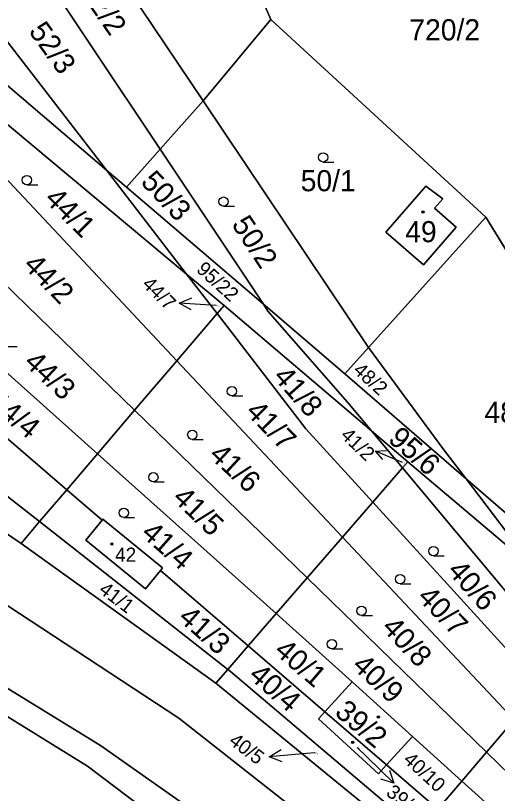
# Model space of a CAD drawing. Extents: x -598233 to -596890, y -1157848 to -1156431.
# Drawn here: x -597365.8 to -597327.1, y -1157018.9 to -1156956.3 of the extents above; entities that cross this region are included whole.
import ezdxf

# ---------------------------------------------------------------- set-up
doc = ezdxf.new("R2010")
doc.units = 0
for name, color, linetype in [('Level 1', 7, 'Continuous'), ('Level 4', 7, 'Continuous'), ('Level 5', 7, 'Continuous'), ('Level 57', 7, 'Continuous'), ('Level 60', 7, 'Continuous'), ('Vrstva 54', 7, 'Continuous'), ('Vrstva 60', 7, 'Continuous')]:
    doc.layers.add(name, color=color, linetype=linetype)

msp = doc.modelspace()

# ---------------------------------------------------------------- linework, layer by layer
at = {"layer": 'Level 1'}
for points in [[(-597345.28, -1156956.63), (-597347.92, -1156950.58), (-597357.71, -1156936.82)], [(-597350.74, -1156963.16), (-597361.74, -1156946.78), (-597363.49, -1156943.72)], [(-597354.19, -1156967.05), (-597365.22, -1156950.5), (-597366.91, -1156947.8)], [(-597316.36, -1157049.69), (-597321.33, -1157045.93), (-597360.03, -1157016.65), (-597390.17, -1156998.02), (-597420.96, -1156981.11), (-597456.97, -1156960.5), (-597484.08, -1156948.02)], [(-597315.54, -1157068.55), (-597316.36, -1157049.69), (-597316.57, -1157044.86), (-597315.03, -1157042.41), (-597313.54, -1157040.04), (-597313.01, -1157039.2), (-597311.84, -1157037.35), (-597310.56, -1157035.31), (-597309.44, -1157033.52), (-597308.22, -1157031.59), (-597306.57, -1157028.96), (-597305.61, -1157027.44), (-597304.81, -1157026.14), (-597303.64, -1157024.31), (-597310.64, -1157014.28), (-597312.61, -1157008.25), (-597315.16, -1156993.14), (-597321.82, -1156982.66), (-597324.52, -1156978.21), (-597328.01, -1156972.52), (-597345.28, -1156956.63), (-597347.92, -1156950.58)], [(-597370.84, -1156952.48), (-597371.09, -1156952.78), (-597370.52, -1156958.47), (-597358.5, -1156968.74)], [(-597370.84, -1156952.48), (-597369.28, -1156954.75), (-597358.5, -1156968.74)], [(-597345.28, -1156956.63), (-597350.74, -1156963.16)], [(-597345.28, -1156956.63), (-597328.01, -1156972.52)], [(-597350.74, -1156963.16), (-597354.19, -1156967.05)], [(-597350.74, -1156963.16), (-597337.44, -1156983)], [(-597352.06, -1156977.11), (-597367.63, -1156964.1)], [(-597369.51, -1156966.31), (-597352.84, -1156984.07)], [(-597354.19, -1156967.05), (-597356.9, -1156970.11)], [(-597354.19, -1156967.05), (-597345.89, -1156979.53)], [(-597358.5, -1156968.74), (-597356.9, -1156970.11)], [(-597358.5, -1156968.74), (-597352.06, -1156977.11)], [(-597356.9, -1156970.11), (-597345.89, -1156979.53)], [(-597332.82, -1156970.02), (-597331.47, -1156971.06), (-597332.13, -1156971.81), (-597330.39, -1156973.32), (-597333.02, -1156976.36), (-597336.04, -1156973.74), (-597332.82, -1156970.02)], [(-597373.63, -1156971.16), (-597356.24, -1156988.05)], [(-597419.12, -1156972.02), (-597386.6, -1156990.52), (-597352.68, -1157012.8), (-597315.03, -1157042.41)], [(-597337.44, -1156983), (-597328.01, -1156972.52)], [(-597312.61, -1157008.25), (-597315.16, -1156993.14), (-597321.82, -1156982.66), (-597324.52, -1156978.21), (-597328.01, -1156972.52)], [(-597349.05, -1156979.62), (-597352.06, -1156977.11)], [(-597352.06, -1156977.11), (-597349.61, -1156980.28)], [(-597422.56, -1156978.13), (-597419.84, -1156979.66), (-597389.18, -1156996.46), (-597358.98, -1157014.99), (-597316.57, -1157044.86)], [(-597380, -1156978.65), (-597361.68, -1156994.44)], [(-597349.05, -1156979.62), (-597349.61, -1156980.28)], [(-597349.05, -1156979.62), (-597337.2, -1156989.71)], [(-597345.89, -1156979.53), (-597339.35, -1156985.13)], [(-597345.89, -1156979.53), (-597345.53, -1156980.07), (-597339.13, -1156987.4), (-597337.2, -1156989.71)], [(-597349.61, -1156980.28), (-597352.84, -1156984.07)], [(-597349.61, -1156980.28), (-597342.48, -1156989.54), (-597337.1, -1156995.44)], [(-597382.92, -1156982.09), (-597363.87, -1156997)], [(-597369.98, -1156981.93), (-597359.22, -1156991.55)], [(-597339.35, -1156985.13), (-597337.44, -1156983)], [(-597329.6, -1156993.56), (-597331.38, -1156991.22), (-597337.44, -1156983)], [(-597352.84, -1156984.07), (-597356.24, -1156988.05)], [(-597352.84, -1156984.07), (-597339.53, -1156998.24)], [(-597385.43, -1156985.04), (-597365.36, -1156998.75)], [(-597339.35, -1156985.13), (-597329.6, -1156993.56)], [(-597356.24, -1156988.05), (-597359.22, -1156991.55)], [(-597356.24, -1156988.05), (-597342.37, -1157001.53)], [(-597337.2, -1156989.71), (-597334.28, -1156992.19)], [(-597334.71, -1156992.68), (-597337.2, -1156989.71)], [(-597359.22, -1156991.55), (-597361.68, -1156994.44)], [(-597359.22, -1156991.55), (-597344.87, -1157004.39)], [(-597334.28, -1156992.19), (-597334.71, -1156992.68)], [(-597324.09, -1157000.8), (-597334.28, -1156992.19)], [(-597334.71, -1156992.68), (-597337.1, -1156995.44)], [(-597334.71, -1156992.68), (-597321.73, -1157008.19)], [(-597329.6, -1156993.56), (-597312.61, -1157008.25)], [(-597329.6, -1156993.56), (-597324.09, -1157000.8)], [(-597361.68, -1156994.44), (-597363.87, -1156997)], [(-597361.68, -1156994.44), (-597358.85, -1156996.88)], [(-597337.1, -1156995.44), (-597339.53, -1156998.24)], [(-597337.1, -1156995.44), (-597323.54, -1157010.33)], [(-597363.87, -1156997), (-597365.36, -1156998.75)], [(-597363.87, -1156997), (-597348.75, -1157008.88)], [(-597358.85, -1156996.88), (-597360.17, -1156998.5), (-597355.37, -1157002.41), (-597354.16, -1157000.92)], [(-597354.16, -1157000.92), (-597353.99, -1157000.72), (-597358.79, -1156996.81), (-597358.85, -1156996.88)], [(-597339.53, -1156998.24), (-597342.37, -1157001.53)], [(-597339.53, -1156998.24), (-597325.74, -1157012.93)], [(-597365.36, -1156998.75), (-597349.72, -1157010)], [(-597354.16, -1157000.92), (-597347.11, -1157006.99)], [(-597342.37, -1157001.53), (-597344.87, -1157004.39)], [(-597342.37, -1157001.53), (-597327.96, -1157015.53)], [(-597344.87, -1157004.39), (-597347.11, -1157006.99)], [(-597344.87, -1157004.39), (-597338.74, -1157009.87)], [(-597347.11, -1157006.99), (-597348.75, -1157008.88)], [(-597347.11, -1157006.99), (-597340.95, -1157012.29)], [(-597348.75, -1157008.88), (-597349.72, -1157010)], [(-597348.75, -1157008.88), (-597348.54, -1157009.04), (-597333.37, -1157021.91)], [(-597338.74, -1157009.87), (-597340.95, -1157012.29)], [(-597333.91, -1157014.29), (-597338.74, -1157009.87)], [(-597349.72, -1157010), (-597334.09, -1157022.76)], [(-597340.95, -1157012.29), (-597341.47, -1157012.86), (-597336.64, -1157017.28), (-597335.99, -1157016.56)], [(-597340.95, -1157012.29), (-597335.99, -1157016.56)], [(-597325.74, -1157012.93), (-597327.96, -1157015.53)], [(-597335.99, -1157016.56), (-597333.91, -1157014.29)], [(-597333.91, -1157014.29), (-597329.94, -1157017.87)], [(-597327.96, -1157015.53), (-597329.94, -1157017.87)], [(-597327.96, -1157015.53), (-597310.75, -1157032.25)], [(-597335.99, -1157016.56), (-597331.86, -1157020.13)], [(-597329.94, -1157017.87), (-597331.86, -1157020.13)], [(-597329.94, -1157017.87), (-597318.23, -1157028.41)]]:
    msp.add_lwpolyline(points, dxfattribs=at)
at = {"layer": 'Level 5'}
for p, q in [((-597341.09, -1156968.09), (-597340.215, -1156968.09)), ((-597364.89, -1156969.92), (-597364.015, -1156969.92)), ((-597349.09, -1156971.65), (-597348.215, -1156971.65)), ((-597366.56, -1156982.93), (-597365.685, -1156982.93)), ((-597348.42, -1156986.89), (-597347.545, -1156986.89)), ((-597351.6, -1156990.39), (-597350.725, -1156990.39)), ((-597354.73, -1156993.81), (-597353.855, -1156993.81)), ((-597357.11, -1156996.67), (-597356.235, -1156996.67)), ((-597332.22, -1156999.75), (-597331.345, -1156999.75)), ((-597334.9, -1157002), (-597334.025, -1157002)), ((-597338, -1157004.55), (-597337.125, -1157004.55)), ((-597340.38, -1157007.23), (-597339.505, -1157007.23))]:
    msp.add_line(p, q, dxfattribs=at)
for centre, radius in [((-597341.09, -1156967.715), 0.375), ((-597364.89, -1156969.545), 0.375), ((-597349.09, -1156971.275), 0.375), ((-597333.05, -1156972.1), 0.09), ((-597333.05, -1156972.1), 0.0521), ((-597348.42, -1156986.515), 0.375), ((-597351.6, -1156990.015), 0.375), ((-597354.73, -1156993.435), 0.375), ((-597357.11, -1156996.295), 0.375), ((-597358.07, -1156998.8), 0.09), ((-597358.07, -1156998.8), 0.0521), ((-597332.22, -1156999.375), 0.375), ((-597334.9, -1157001.625), 0.375), ((-597338, -1157004.175), 0.375), ((-597340.38, -1157006.855), 0.375), ((-597336.64, -1157012.7), 0.09), ((-597336.64, -1157012.7), 0.0521), ((-597338.72, -1157014.75), 0.09), ((-597338.72, -1157014.75), 0.0521)]:
    msp.add_circle(centre, radius, dxfattribs=at)
at = {"layer": 'Level 57'}
for p, q in [((-597349.69, -1156979.62), (-597352.646, -1156979.432)), ((-597334.71, -1156992.24), (-597336.869, -1156991.349)), ((-597338.35, -1157015.16), (-597337.54, -1157015.948)), ((-597342.421, -1157015.655), (-597345.411, -1157015.902)), ((-597341.76, -1157015.6), (-597342.421, -1157015.655)), ((-597337.54, -1157015.948), (-597335.39, -1157018.04))]:
    msp.add_line(p, q, dxfattribs=at)
for points in [[(-597351.692, -1156979.987), (-597352.646, -1156979.432), (-597351.629, -1156979.002)], [(-597336.298, -1156992.006), (-597336.869, -1156991.349), (-597336.001, -1156991.286)], [(-597344.373, -1157016.318), (-597345.411, -1157015.902), (-597344.455, -1157015.321)], [(-597335.758, -1157016.984), (-597335.39, -1157018.04), (-597336.455, -1157017.701)]]:
    msp.add_lwpolyline(points, dxfattribs=at)
at = {"layer": 'Level 60'}
for points in [[(-597451.05, -1156953.86), (-597464.61, -1156946.36), (-597548.33, -1156902.86), (-597534.86, -1156896.71), (-597497.72, -1156917.84), (-597462.51, -1156937.89), (-597461.2, -1156938.63), (-597445.67, -1156947.81), (-597407.63, -1156970.82), (-597406.11, -1156971.52), (-597385.43, -1156985.04), (-597365.36, -1156998.75), (-597349.72, -1157010), (-597334.09, -1157022.76), (-597314.86, -1157038.93), (-597313.54, -1157040.04), (-597315.03, -1157042.41), (-597352.68, -1157012.8), (-597386.6, -1156990.52), (-597419.12, -1156972.02)], [(-597405.88, -1156927.58), (-597393.79, -1156938.04), (-597383.92, -1156946.41), (-597381.56, -1156948), (-597378.88, -1156947.67), (-597375.93, -1156946.59), (-597375.26, -1156946.02), (-597370.84, -1156952.48), (-597371.09, -1156952.78), (-597370.52, -1156958.47), (-597358.5, -1156968.74), (-597352.06, -1156977.11), (-597367.63, -1156964.1), (-597384.93, -1156949.57), (-597385.23, -1156949.57)], [(-597350.74, -1156963.16), (-597361.74, -1156946.78), (-597363.49, -1156943.72), (-597357.71, -1156936.82), (-597347.92, -1156950.58), (-597345.28, -1156956.63)], [(-597354.19, -1156967.05), (-597365.22, -1156950.5), (-597366.91, -1156947.8), (-597363.49, -1156943.72), (-597361.74, -1156946.78), (-597350.74, -1156963.16)], [(-597365.22, -1156950.5), (-597354.19, -1156967.05), (-597356.9, -1156970.11), (-597358.5, -1156968.74), (-597369.28, -1156954.75), (-597370.84, -1156952.48), (-597366.91, -1156947.8)], [(-597419.84, -1156979.66), (-597389.18, -1156996.46), (-597358.98, -1157014.99), (-597316.57, -1157044.86), (-597316.36, -1157049.69), (-597321.33, -1157045.93), (-597360.03, -1157016.65), (-597390.17, -1156998.02), (-597420.96, -1156981.11), (-597456.97, -1156960.5), (-597484.08, -1156948.02), (-597453.24, -1156960.9), (-597422.56, -1156978.13)], [(-597370.52, -1156958.47), (-597371.09, -1156952.78), (-597370.84, -1156952.48), (-597369.28, -1156954.75), (-597358.5, -1156968.74)], [(-597328.01, -1156972.52), (-597337.44, -1156983), (-597350.74, -1156963.16), (-597345.28, -1156956.63)], [(-597339.35, -1156985.13), (-597345.89, -1156979.53), (-597354.19, -1156967.05), (-597350.74, -1156963.16), (-597337.44, -1156983)], [(-597367.63, -1156964.1), (-597352.06, -1156977.11), (-597349.61, -1156980.28), (-597352.84, -1156984.07), (-597369.51, -1156966.31)], [(-597356.24, -1156988.05), (-597373.63, -1156971.16), (-597369.51, -1156966.31), (-597352.84, -1156984.07)], [(-597345.89, -1156979.53), (-597356.9, -1156970.11), (-597354.19, -1156967.05)], [(-597345.89, -1156979.53), (-597345.53, -1156980.07), (-597339.13, -1156987.4), (-597337.2, -1156989.71), (-597349.05, -1156979.62), (-597352.06, -1156977.11), (-597358.5, -1156968.74), (-597356.9, -1156970.11)], [(-597332.82, -1156970.02), (-597331.47, -1156971.06), (-597332.13, -1156971.81), (-597330.39, -1156973.32), (-597333.02, -1156976.36), (-597336.04, -1156973.74)], [(-597331.47, -1156971.06), (-597332.82, -1156970.02), (-597336.04, -1156973.74), (-597333.02, -1156976.36), (-597330.39, -1156973.32), (-597332.13, -1156971.81)], [(-597370.83, -1156977.22), (-597371.37, -1156977.81), (-597372.33, -1156976.94), (-597373.78, -1156978.53), (-597377.25, -1156975.42), (-597373.63, -1156971.16), (-597356.24, -1156988.05), (-597359.22, -1156991.55), (-597369.98, -1156981.93), (-597368.83, -1156980.66), (-597368.38, -1156981.07), (-597368.11, -1156980.77), (-597368.56, -1156980.37), (-597368.02, -1156979.78)], [(-597389.18, -1156996.46), (-597419.84, -1156979.66), (-597422.56, -1156978.13), (-597419.12, -1156972.02), (-597386.6, -1156990.52), (-597352.68, -1157012.8), (-597315.03, -1157042.41), (-597316.57, -1157044.86), (-597358.98, -1157014.99)], [(-597312.61, -1157008.25), (-597329.6, -1156993.56), (-597331.38, -1156991.22), (-597337.44, -1156983), (-597328.01, -1156972.52), (-597324.52, -1156978.21), (-597321.82, -1156982.66), (-597315.16, -1156993.14)], [(-597374.55, -1156979.38), (-597370.78, -1156982.81), (-597369.98, -1156981.93), (-597359.22, -1156991.55), (-597361.68, -1156994.44), (-597380, -1156978.65), (-597377.25, -1156975.42), (-597373.78, -1156978.53)], [(-597352.06, -1156977.11), (-597349.05, -1156979.62), (-597349.61, -1156980.28)], [(-597363.87, -1156997), (-597382.92, -1156982.09), (-597380, -1156978.65), (-597361.68, -1156994.44)], [(-597349.05, -1156979.62), (-597337.2, -1156989.71), (-597334.71, -1156992.68), (-597337.1, -1156995.44), (-597342.48, -1156989.54), (-597349.61, -1156980.28)], [(-597339.35, -1156985.13), (-597329.6, -1156993.56), (-597324.09, -1157000.8), (-597334.28, -1156992.19), (-597337.2, -1156989.71), (-597339.13, -1156987.4), (-597345.53, -1156980.07), (-597345.89, -1156979.53)], [(-597349.61, -1156980.28), (-597342.48, -1156989.54), (-597337.1, -1156995.44), (-597339.53, -1156998.24), (-597352.84, -1156984.07)], [(-597365.36, -1156998.75), (-597385.43, -1156985.04), (-597382.92, -1156982.09), (-597363.87, -1156997)], [(-597329.6, -1156993.56), (-597339.35, -1156985.13), (-597337.44, -1156983), (-597331.38, -1156991.22)], [(-597342.37, -1157001.53), (-597356.24, -1156988.05), (-597352.84, -1156984.07), (-597339.53, -1156998.24)], [(-597344.87, -1157004.39), (-597359.22, -1156991.55), (-597356.24, -1156988.05), (-597342.37, -1157001.53)], [(-597334.28, -1156992.19), (-597334.71, -1156992.68), (-597337.2, -1156989.71)], [(-597353.99, -1157000.72), (-597358.79, -1156996.81), (-597358.85, -1156996.88), (-597361.68, -1156994.44), (-597359.22, -1156991.55), (-597344.87, -1157004.39), (-597347.11, -1157006.99), (-597354.16, -1157000.92)], [(-597320, -1157006.16), (-597321.73, -1157008.19), (-597334.71, -1156992.68), (-597334.28, -1156992.19), (-597324.09, -1157000.8)], [(-597334.71, -1156992.68), (-597321.73, -1157008.19), (-597323.54, -1157010.33), (-597337.1, -1156995.44)], [(-597315.42, -1157008.06), (-597319.06, -1157005.05), (-597324.09, -1157000.8), (-597329.6, -1156993.56), (-597312.61, -1157008.25), (-597310.64, -1157014.28), (-597303.64, -1157024.31), (-597304.81, -1157026.14), (-597307.97, -1157021.99), (-597308.81, -1157018.97), (-597311.74, -1157015.11)], [(-597360.17, -1156998.5), (-597355.37, -1157002.41), (-597354.16, -1157000.92), (-597347.11, -1157006.99), (-597348.75, -1157008.88), (-597363.87, -1156997), (-597361.68, -1156994.44), (-597358.85, -1156996.88)], [(-597337.1, -1156995.44), (-597323.54, -1157010.33), (-597325.74, -1157012.93), (-597339.53, -1156998.24)], [(-597349.72, -1157010), (-597365.36, -1156998.75), (-597363.87, -1156997), (-597348.75, -1157008.88)], [(-597355.37, -1157002.41), (-597360.17, -1156998.5), (-597358.85, -1156996.88), (-597358.79, -1156996.81), (-597353.99, -1157000.72), (-597354.16, -1157000.92)], [(-597327.96, -1157015.53), (-597342.37, -1157001.53), (-597339.53, -1156998.24), (-597325.74, -1157012.93)], [(-597333.91, -1157014.29), (-597338.74, -1157009.87), (-597344.87, -1157004.39), (-597342.37, -1157001.53), (-597327.96, -1157015.53), (-597329.94, -1157017.87)], [(-597338.74, -1157009.87), (-597340.95, -1157012.29), (-597347.11, -1157006.99), (-597344.87, -1157004.39)], [(-597341.47, -1157012.86), (-597336.64, -1157017.28), (-597335.99, -1157016.56), (-597331.86, -1157020.13), (-597333.37, -1157021.91), (-597348.54, -1157009.04), (-597348.75, -1157008.88), (-597347.11, -1157006.99), (-597340.95, -1157012.29)], [(-597334.09, -1157022.76), (-597349.72, -1157010), (-597348.75, -1157008.88), (-597348.54, -1157009.04), (-597333.37, -1157021.91)], [(-597338.74, -1157009.87), (-597333.91, -1157014.29), (-597335.99, -1157016.56), (-597340.95, -1157012.29)], [(-597336.64, -1157017.28), (-597341.47, -1157012.86), (-597340.95, -1157012.29), (-597335.99, -1157016.56)], [(-597310.75, -1157032.25), (-597327.96, -1157015.53), (-597325.74, -1157012.93), (-597309.51, -1157030.22)], [(-597335.99, -1157016.56), (-597333.91, -1157014.29), (-597329.94, -1157017.87), (-597331.86, -1157020.13)], [(-597329.94, -1157017.87), (-597327.96, -1157015.53), (-597310.75, -1157032.25), (-597311.89, -1157034.11), (-597313.29, -1157032.85), (-597312.81, -1157032.3), (-597317.85, -1157027.96), (-597318.23, -1157028.41)], [(-597331.86, -1157020.13), (-597329.94, -1157017.87), (-597318.23, -1157028.41), (-597319.94, -1157030.39)]]:
    msp.add_lwpolyline(points, close=True, dxfattribs=at)
for points in [[(-597315.54, -1157068.55), (-597316.36, -1157049.69), (-597316.57, -1157044.86), (-597315.03, -1157042.41), (-597313.54, -1157040.04), (-597313.01, -1157039.2), (-597311.84, -1157037.35), (-597310.56, -1157035.31), (-597309.44, -1157033.52), (-597308.22, -1157031.59), (-597306.57, -1157028.96), (-597305.61, -1157027.44), (-597304.81, -1157026.14), (-597303.64, -1157024.31), (-597310.64, -1157014.28), (-597312.61, -1157008.25), (-597315.16, -1156993.14), (-597321.82, -1156982.66), (-597324.52, -1156978.21), (-597328.01, -1156972.52), (-597345.28, -1156956.63), (-597347.92, -1156950.58)], [(-597390.17, -1156998.02), (-597360.03, -1157016.65), (-597321.33, -1157045.93), (-597316.36, -1157049.69), (-597315.54, -1157068.55), (-597313.81, -1157082.16), (-597323.95, -1157090.2), (-597350.78, -1157099.58), (-597386.77, -1157115.26)]]:
    msp.add_lwpolyline(points, dxfattribs=at)
at = {"layer": 'Vrstva 54'}
for p, q in [((-597347.92, -1156950.58), (-597345.28, -1156956.63)), ((-597345.28, -1156956.63), (-597328.01, -1156972.52)), ((-597328.01, -1156972.52), (-597324.52, -1156978.21))]:
    msp.add_line(p, q, dxfattribs=at)
at = {"layer": 'Vrstva 60'}
for points in [[(-597347.92, -1156950.58), (-597345.28, -1156956.63), (-597328.01, -1156972.52), (-597324.52, -1156978.21), (-597321.82, -1156982.66), (-597315.16, -1156993.14), (-597312.61, -1157008.25), (-597310.64, -1157014.28), (-597303.64, -1157024.31), (-597304.81, -1157026.14), (-597305.61, -1157027.44), (-597306.57, -1157028.96), (-597308.22, -1157031.59), (-597309.44, -1157033.52), (-597310.56, -1157035.31), (-597311.84, -1157037.35), (-597313.01, -1157039.2), (-597313.54, -1157040.04), (-597315.03, -1157042.41), (-597316.57, -1157044.86), (-597315.54, -1157068.55)], [(-597315.54, -1157068.55), (-597316.57, -1157044.86), (-597315.03, -1157042.41), (-597313.54, -1157040.04), (-597313.01, -1157039.2), (-597311.84, -1157037.35), (-597310.56, -1157035.31), (-597309.44, -1157033.52), (-597308.22, -1157031.59), (-597306.57, -1157028.96), (-597305.61, -1157027.44), (-597304.81, -1157026.14), (-597303.64, -1157024.31), (-597310.64, -1157014.28), (-597312.61, -1157008.25), (-597315.16, -1156993.14), (-597321.82, -1156982.66), (-597324.52, -1156978.21), (-597328.01, -1156972.52), (-597345.28, -1156956.63), (-597347.92, -1156950.58)]]:
    msp.add_lwpolyline(points, dxfattribs=at)

# ---------------------------------------------------------------- texts
at = {"layer": 'Level 4'}
for s, height, rotation, p in [('52/2', 1.7, 304.33698, (-597360.68, -1156954.4)), ('52/3', 1.7, 305.71641, (-597364.8, -1156957.586)), ('50/3', 1.7, 313.29189, (-597355.82, -1156969.76)), ('44/1', 1.7, 315, (-597363.565, -1156971.155)), ('50/2', 1.7, 303.14871, (-597348.49, -1156973.1)), ('44/2', 1.7, 313.96176, (-597365.266, -1156976.451)), ('95/22', 1.14, 317.75013, (-597351.349, -1156976.825)), ('44/7', 0.1, 315.11889, (-597349.69, -1156979.62)), ('44/3', 1.7, 317.13426, (-597365.221, -1156984.331)), ('41/8', 1.7, 311.45931, (-597345.181, -1156985.412)), ('48/2', 1.14, 317.44836, (-597338.743, -1156984.939)), ('44/4', 1.7, 320.445, (-597368.157, -1156987.628)), ('41/7', 1.7, 314.22528, (-597347.4, -1156988.251)), ('95/6', 1.7, 318.69729, (-597335.95, -1156990.49)), ('41/6', 1.7, 317.12913, (-597350.339, -1156991.772)), ('41/2', 0.1, 316.09575, (-597334.71, -1156992.24)), ('41/5', 1.7, 316.14678, (-597353.274, -1156995.217)), ('41/4', 1.7, 318.57156, (-597355.805, -1156998.081)), ('40/6', 1.7, 311.61753, (-597331.174, -1157001.012)), ('41/1', 1.14, 322.65639, (-597359.188, -1157002.649)), ('40/7', 1.7, 313.93548, (-597333.592, -1157003.155)), ('41/3', 1.7, 318.42126, (-597352.819, -1157004.866)), ('40/8', 1.7, 313.0011, (-597336.459, -1157005.589)), ('40/1', 1.7, 319.2498, (-597345.109, -1157007.545)), ('40/9', 1.7, 316.99206, (-597338.848, -1157008.703)), ('40/4', 1.7, 318.83535, (-597347.16, -1157009.511)), ('39/2', 1.7, 320.08329, (-597340.246, -1157012.485)), ('39/1', 0.1, 321.18858, (-597338.35, -1157015.16)), ('40/5', 0.1, 322.8246, (-597341.76, -1157015.6)), ('40/10', 1.14, 317.32938, (-597334.717, -1157016.249))]:
    msp.add_text(s, height=height, rotation=rotation, dxfattribs=at).set_placement(p)
for s, height, p in [('720/2', 1.7, (-597334.157, -1156958.31)), ('50/1', 1.7, (-597342.89, -1156970.44)), ('49', 1.7, (-597334.49, -1156974.54)), ('48/1', 1.7, (-597328.12, -1156989.06)), ('42', 1.14, (-597357.807, -1157000.23))]:
    msp.add_text(s, height=height, dxfattribs=at).set_placement(p)
at = {"layer": 'Level 57'}
for s, rotation, p in [('44/7', 315.11889, (-597355.704, -1156977.996)), ('41/2', 316.09575, (-597339.753, -1156990.155)), ('40/5', 322.8246, (-597348.741, -1157014.807)), ('39/1', 321.18858, (-597336.105, -1157018.928))]:
    msp.add_text(s, height=1.14, rotation=rotation, dxfattribs=at).set_placement(p)

doc.saveas('drawing.dxf')
